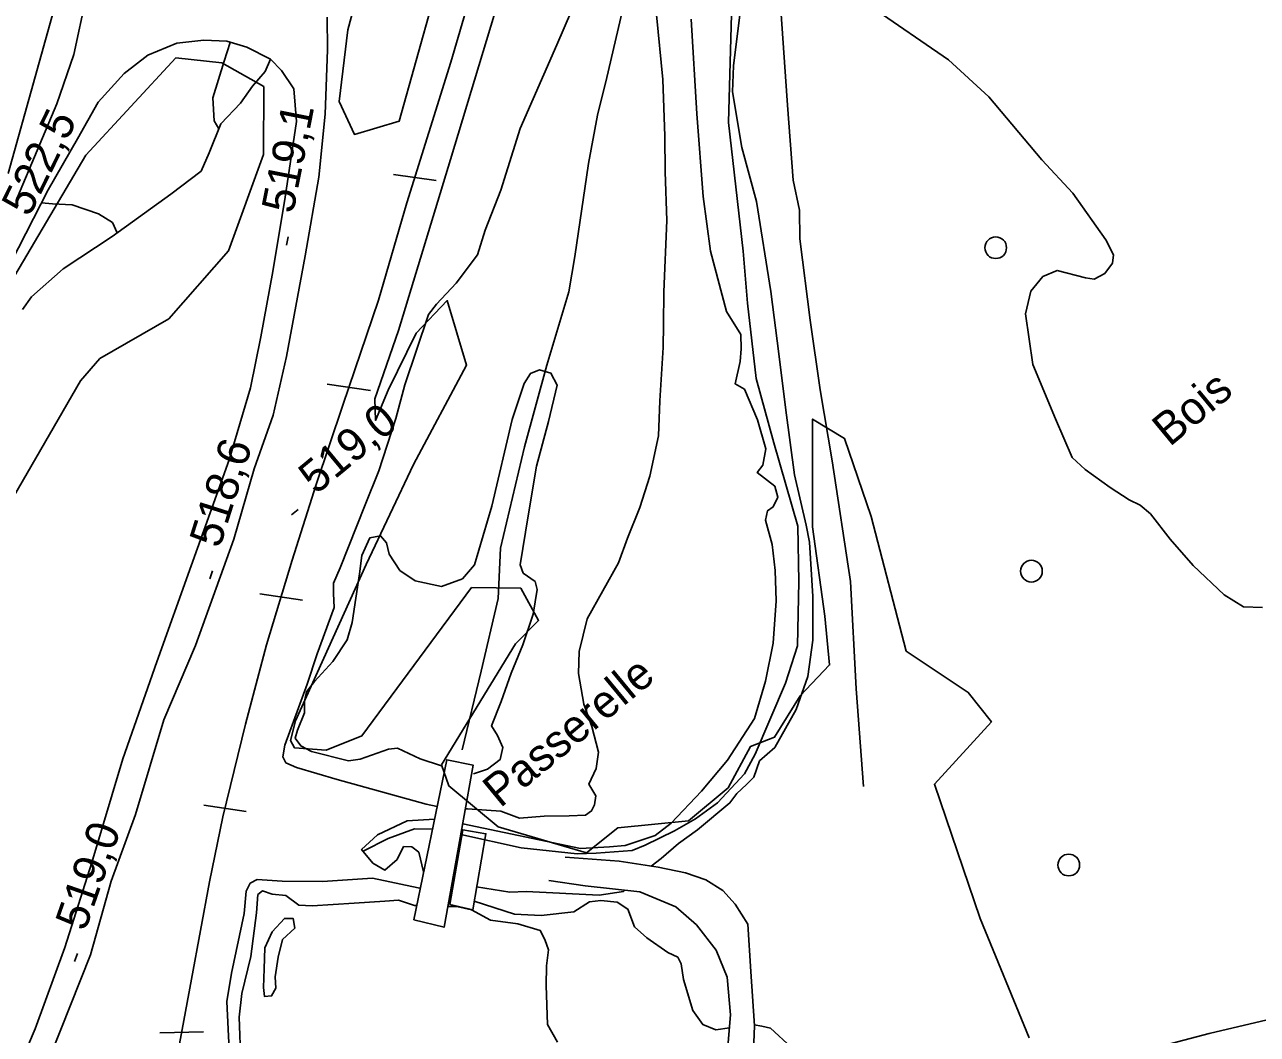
# Model space of a CAD drawing. Extents: x 347059 to 352153, y 6073752 to 6078601.
# Drawn here: x 347588.7 to 347759, y 6075388.2 to 6075527.7 of the extents above; entities that cross this region are included whole.
import ezdxf

# ---------------------------------------------------------------- set-up
doc = ezdxf.new("R2010")
doc.units = 0
for name, color, linetype in [('Level 1', 7, 'Continuous'), ('Level 19', 7, 'Continuous'), ('Level 2', 7, 'Continuous'), ('Level 22', 7, 'Continuous'), ('Level 23', 7, 'Continuous'), ('Level 26', 7, 'Continuous'), ('Level 3', 7, 'Continuous'), ('Level 31', 7, 'Continuous'), ('Level 36', 7, 'Continuous'), ('Level 4', 7, 'Continuous'), ('Level 44', 7, 'Continuous'), ('Level 54', 7, 'Continuous')]:
    doc.layers.add(name, color=color, linetype=linetype)

msp = doc.modelspace()

# ---------------------------------------------------------------- linework, layer by layer
at = {"layer": 'Level 1'}
for points in [[(347652.33, 6075499.3), (347654.48, 6075504.82), (347657.14, 6075513.31), (347662.23, 6075524.88), (347669.46, 6075541.69), (347673.43, 6075553.21), (347674.57, 6075556.8), (347676.01, 6075557.93), (347677.25, 6075556.76), (347677.37, 6075552.62), (347676.98, 6075547), (347676.29, 6075536.62), (347676, 6075529.02), (347676.85, 6075520.07), (347677.13, 6075512.28), (347677.18, 6075507.36), (347677.42, 6075500.6), (347676.99, 6075490.74), (347676.94, 6075486.27)], [(347615.52, 6075513.28), (347614.88, 6075514.4), (347614.66, 6075517.57), (347616.25, 6075522.63), (347617.08, 6075525.18), (347617.09, 6075525.23)], [(347645.68, 6075419.67), (347644.16, 6075420.01), (347638.69, 6075421.53), (347631.86, 6075423.39), (347626.26, 6075425.06), (347624.77, 6075425.71), (347624.34, 6075426.55), (347624.64, 6075428.14), (347627.73, 6075436.57), (347629.09, 6075440.77), (347631.47, 6075447.15), (347631.36, 6075449.07), (347631.35, 6075450.53), (347632.29, 6075452.65), (347635.71, 6075461.35), (347637.63, 6075466.02), (347639.95, 6075473.28), (347641.2, 6075477.93), (347644.49, 6075487.61), (347645.59, 6075489.05), (347648.3, 6075491.96), (347651.26, 6075495.87), (347652.33, 6075499.3)], [(347676.94, 6075486.27), (347676.92, 6075483.05), (347676.44, 6075475.69), (347676.28, 6075470.86), (347675.08, 6075465.32), (347673.7, 6075460.98), (347671.97, 6075456.73), (347670.75, 6075453.32), (347666.39, 6075445.58), (347665.3, 6075441.06), (347665.23, 6075438.06), (347665.93, 6075433.82), (347667.04, 6075430.71), (347667.96, 6075427.19), (347667.67, 6075424.94), (347666.65, 6075422.76), (347667.6, 6075421.14), (347667.41, 6075419.91), (347667.03, 6075419.06), (347666.2, 6075418.47), (347663.94, 6075418.39), (347660.46, 6075418.33), (347657.04, 6075418.05), (347654.47, 6075419.02), (347649.87, 6075419.36), (347649.59, 6075419.34)], [(347616.93, 6075386.06), (347616.61, 6075392.75), (347617.27, 6075396.65), (347619.02, 6075404.91), (347619.31, 6075407.96), (347619.86, 6075409.08), (347620.8, 6075409.58), (347624.24, 6075409.35), (347629.84, 6075409.29), (347636.75, 6075409.76), (347643.08, 6075408.43), (347643.34, 6075408.37)], [(347647.43, 6075407.42), (347647.64, 6075407.37)], [(347650.79, 6075406.59), (347656.36, 6075404.78), (347660.04, 6075404.6), (347664.59, 6075405.14), (347666.72, 6075406.49), (347668.29, 6075406.71), (347670.55, 6075406.44), (347672.02, 6075405.5), (347672.96, 6075403.07), (347674.66, 6075401.52), (347677.57, 6075399.5), (347678.92, 6075398.87), (347679.42, 6075397.94), (347679.73, 6075395.79), (347681.02, 6075391.5), (347682.39, 6075389.54), (347684.21, 6075388.82), (347686.08, 6075389.11)], [(347689.51, 6075389.52), (347690.57, 6075389.32), (347691.73, 6075389.07), (347694.65, 6075386.39), (347695.16, 6075384.8), (347696.77, 6075380.77), (347697.8, 6075378.41), (347700.19, 6075375.55), (347702.56, 6075374.82), (347704.49, 6075375.6), (347705.09, 6075376.5), (347705.84, 6075376.58), (347707.63, 6075373.43)]]:
    msp.add_lwpolyline(points, dxfattribs=at)
at = {"layer": 'Level 19'}
for points in [[(347587.68, 6075503.86), (347593.13, 6075516.73), (347595.49, 6075523.54), (347597.17, 6075531.51)], [(347630.5, 6075528.69), (347630.54, 6075524.17), (347630.22, 6075515.32), (347629.34, 6075506.59), (347627.42, 6075495.74), (347624.86, 6075481.84), (347623, 6075473.71), (347620.39, 6075466.29), (347617.6, 6075456.6), (347612.3, 6075441.92), (347607.89, 6075431.66), (347604, 6075418.58), (347600.64, 6075409.38), (347597.78, 6075399.16), (347589.46, 6075378.31)], [(347586.72, 6075380.96), (347590.11, 6075388.97), (347594.23, 6075400.2), (347597.98, 6075411.94), (347602.24, 6075426.25), (347606.96, 6075439.67), (347611.68, 6075452.92), (347616.94, 6075467.56), (347619.9, 6075477.49), (347621.31, 6075484.55), (347622.98, 6075493.59), (347624.67, 6075503.84), (347626.24, 6075514.31), (347625.87, 6075518.78), (347624.19, 6075521.35), (347622.63, 6075522.89), (347619.37, 6075524.56), (347616.62, 6075525.37), (347613.45, 6075525.53), (347609.72, 6075525.11), (347605.7, 6075523.46), (347602.42, 6075520.94), (347598.84, 6075516.94), (347595.99, 6075511.91), (347591.94, 6075504.86), (347586.83, 6075494.84)], [(347663.35, 6075412.65), (347670.82, 6075412.1), (347676.22, 6075411.29), (347680, 6075410.52), (347682.83, 6075409.53), (347685.16, 6075408.05), (347686.86, 6075406.17), (347688.62, 6075403.43), (347689.05, 6075396.88), (347689.52, 6075389.39), (347689.23, 6075381.39)], [(347661.12, 6075409.43), (347666.13, 6075408.73), (347673.69, 6075407.89), (347678.68, 6075405.8), (347681.51, 6075403.31), (347684.24, 6075399.81), (347685.76, 6075396.11), (347686.24, 6075390.9), (347685.56, 6075383.26), (347684.33, 6075376.97), (347683.89, 6075375.19), (347682.62, 6075370.18), (347681.29, 6075363.47), (347679.94, 6075354.9), (347679.94, 6075354.9), (347679.03, 6075348.13), (347677.75, 6075337.71), (347677.34, 6075335.16), (347674.08, 6075335.3), (347671.55, 6075336.83), (347669.29, 6075339.28), (347668.04, 6075341.6)]]:
    msp.add_lwpolyline(points, dxfattribs=at)
at = {"layer": 'Level 2'}
for points in [[(347705.63, 6075530.16), (347716.36, 6075522.8), (347721.92, 6075517.68), (347729.24, 6075508.98), (347733.54, 6075504.41), (347738.1, 6075497.93), (347739.14, 6075495.87), (347739.03, 6075494.72), (347737.95, 6075493.29), (347736.49, 6075492.49), (347735.27, 6075492.68), (347731.36, 6075493.71), (347729.39, 6075492.89), (347727.74, 6075490.86), (347727.01, 6075487.73), (347728.02, 6075480.72), (347731.15, 6075473.23), (347733.43, 6075467.9), (347735.23, 6075466.2), (347738.71, 6075463.75), (347741.32, 6075462.04)], [(347680.8, 6075528.42), (347681.56, 6075515.37), (347682.46, 6075503.91), (347683.45, 6075496.4), (347685.68, 6075488.06), (347687.67, 6075484.87), (347687.7, 6075482.88), (347687.54, 6075481.14), (347686.87, 6075478.04), (347688.14, 6075477.34), (347689.95, 6075473.07), (347691.12, 6075469.07), (347690.68, 6075466.83), (347689.92, 6075465.8), (347692.33, 6075463.9), (347692.78, 6075462.39), (347692.13, 6075461.05)], [(347696.7, 6075458.51), (347695.07, 6075465.49), (347693.85, 6075474.41), (347692.9, 6075482.2), (347691.8, 6075490.82), (347689.8, 6075503.26), (347687.78, 6075510.71), (347686.51, 6075518.38), (347686.63, 6075521.97), (347687.53, 6075529.01)], [(347601.47, 6075498.92), (347600.83, 6075500.33), (347598.88, 6075501.53), (347595.25, 6075502.8), (347592.53, 6075502.9), (347591.02, 6075503.05)], [(347646.26, 6075425.3), (347643.33, 6075426.27), (347640.22, 6075427.72), (347638.96, 6075427.61), (347635.05, 6075426.19), (347633.42, 6075425.99), (347628.31, 6075427.25), (347626.84, 6075428.04), (347626.06, 6075429.13), (347626.39, 6075430.2), (347627.35, 6075432.6), (347627.36, 6075434.21), (347627.63, 6075435.5), (347628.72, 6075436.94), (347631.27, 6075439.71), (347633.25, 6075442.68), (347633.93, 6075445.11), (347634.94, 6075451.82), (347635.25, 6075454.35), (347636.39, 6075456.8), (347637.87, 6075457.04), (347638.66, 6075456.09), (347639.03, 6075454.53), (347640.51, 6075452.27), (347642.65, 6075450.84), (347646.27, 6075450.08), (347649.17, 6075451.13), (347650.83, 6075453.03), (347653.23, 6075461.16), (347656.07, 6075473.13), (347657.72, 6075478.1), (347658.59, 6075479.49), (347659.84, 6075479.98), (347661.4, 6075479.53), (347662.27, 6075477.85), (347661.05, 6075472.83), (347659.43, 6075466.68), (347658.26, 6075459.84), (347657.17, 6075453.05), (347657.58, 6075451.92), (347659.24, 6075450.75), (347659.5, 6075449.63), (347658.95, 6075446.24), (347657.51, 6075441.98), (347655.89, 6075438.1), (347654.55, 6075434.19), (347653.2, 6075430.8), (347654.03, 6075429.48), (347654.76, 6075427.81), (347654.38, 6075426.16), (347652.63, 6075424.85), (347650.7, 6075424.18)], [(347692.13, 6075461.05), (347691.34, 6075460.53), (347691.07, 6075459.23), (347692, 6075455.85), (347692.4, 6075452.29), (347692.52, 6075448.09), (347692.11, 6075442.25), (347691.08, 6075436.99), (347689.56, 6075431.84), (347685.82, 6075426.08), (347682.23, 6075421.77), (347678.03, 6075417.38), (347675.79, 6075415.67), (347671.67, 6075414.28), (347669.5, 6075414.1), (347665.49, 6075413.88), (347649.22, 6075417.3)], [(347741.32, 6075462.04), (347742.85, 6075461.31), (347744.27, 6075460.08), (347747, 6075456.61), (347750.15, 6075452.96), (347754.43, 6075448.9), (347757.12, 6075447.26), (347759.73, 6075447.15)], [(347675.28, 6075411.43), (347676.63, 6075412.49), (347679.02, 6075414.57), (347681.64, 6075416.47), (347686.14, 6075420.17), (347687.08, 6075421.48), (347688.41, 6075422.7), (347689.46, 6075423.72), (347690.25, 6075425.97), (347692.36, 6075427.84), (347695.3, 6075433.08), (347696.92, 6075437.64), (347697.62, 6075442.64), (347697.61, 6075448.67), (347697.14, 6075456.2), (347696.7, 6075458.51)], [(347645.31, 6075417.9), (347641.56, 6075417.68), (347637.42, 6075415.78), (347635.24, 6075413.75), (347636.81, 6075411.83), (347638.45, 6075410.9), (347640.15, 6075412.36), (347641.05, 6075414.13), (347642.2, 6075414.12), (347643.16, 6075413.36), (347643.81, 6075410.63)], [(347647.74, 6075409.09), (347647.94, 6075409.06)], [(347651.14, 6075408.56), (347655.74, 6075407.85), (347657.96, 6075407.95), (347668.05, 6075407.41), (347671.43, 6075407.91), (347671.64, 6075408.12)], [(347642.85, 6075405.99), (347642.55, 6075406.01), (347640.35, 6075406.72), (347638.43, 6075406.6), (347634.2, 6075406.32), (347628.42, 6075405.96), (347626.58, 6075406.05), (347624.79, 6075407.38), (347622.9, 6075407.55), (347621.54, 6075408.04), (347620.9, 6075407.51), (347620.73, 6075404.97), (347619.94, 6075398.97), (347618.71, 6075393.82), (347618.32, 6075390.56), (347618.54, 6075384.33)], [(347662.29, 6075387.12), (347660.91, 6075389.58), (347660.75, 6075394.94), (347660.79, 6075397.64), (347661.08, 6075399.88), (347660.55, 6075401.32), (347659.93, 6075402.56), (347656.85, 6075403.48), (347653.06, 6075403.97), (347650.42, 6075405.38), (347648.38, 6075405.85), (347647.15, 6075405.84)], [(347621.69, 6075394.66), (347621.76, 6075397.25), (347621.86, 6075400.16), (347622.87, 6075402.34), (347624.58, 6075404.22), (347625.79, 6075404.19), (347626, 6075402.87), (347624.32, 6075401.32), (347623.69, 6075398.86), (347623.28, 6075396.14), (347623.38, 6075394.59), (347622.8, 6075393.51), (347621.82, 6075393.43), (347621.69, 6075394.66)]]:
    msp.add_lwpolyline(points, dxfattribs=at)
at = {"layer": 'Level 22'}
for points in [[(347704.6, 6075422.45), (347703.58, 6075435.93), (347702.82, 6075450.77), (347700.28, 6075467.42), (347698.63, 6075477.24), (347697.24, 6075486.83), (347695.82, 6075498.06), (347695.74, 6075502.02), (347694.86, 6075506.19), (347694.1, 6075516.55), (347692.97, 6075532.44), (347692.17, 6075545.42), (347691.99, 6075558.55), (347692.74, 6075566.82), (347693.27, 6075572.27), (347694.1, 6075584.23), (347694.82, 6075596.85), (347695.19, 6075610.31), (347695.4, 6075619.03), (347696.28, 6075626.27), (347697.12, 6075631.98)], [(347649.12, 6075427.51), (347651.78, 6075438.36), (347654.13, 6075448.42), (347654.43, 6075455.34), (347657.77, 6075469.35), (347660.82, 6075480.62), (347663.87, 6075490.75), (347664.71, 6075495.65), (347666.62, 6075508.51), (347667.84, 6075515.17), (347669.11, 6075520.36), (347671.58, 6075530.83)]]:
    msp.add_lwpolyline(points, dxfattribs=at)
at = {"layer": 'Level 23'}
for p, q in [((347639.63, 6075506.99), (347645.56, 6075506.12)), ((347630.49, 6075478.01), (347636.45, 6075477.14)), ((347621.16, 6075449.05), (347627.08, 6075448.18)), ((347613.42, 6075419.86), (347619.31, 6075419)), ((347607.35, 6075388.43), (347613.4, 6075388.56))]:
    msp.add_line(p, q, dxfattribs=at)
msp.add_lwpolyline([(347609.23, 6075382.41), (347611.75, 6075395.83), (347614.2, 6075409.25), (347616.07, 6075418.24), (347619.2, 6075431.04), (347622.12, 6075441.98), (347625.66, 6075453.7), (347628.94, 6075464.13), (347632.63, 6075475.13), (347637.59, 6075489.59), (347641.51, 6075503.06), (347647.56, 6075522.49), (347652.71, 6075540.14), (347658.57, 6075559.61), (347664.03, 6075579.1), (347668.39, 6075594.32), (347673.93, 6075613.79), (347677.32, 6075624.7), (347681.41, 6075639.01), (347686.09, 6075655.26), (347691.07, 6075673.19)], dxfattribs=at)
at = {"layer": 'Level 26'}
msp.add_lwpolyline([(347642.44, 6075404.01), (347647.01, 6075426.12), (347650.68, 6075425.36), (347646.63, 6075403), (347642.44, 6075404.01)], dxfattribs=at)
at = {"layer": 'Level 3'}
for p, q in [((347624.87, 6075497.21), (347625.11, 6075498.38)), ((347625.57, 6075459.94), (347626.49, 6075460.71)), ((347614.28, 6075451.1), (347614.64, 6075452.24)), ((347595.56, 6075398.24), (347595.96, 6075399.38))]:
    msp.add_line(p, q, dxfattribs=at)
at = {"layer": 'Level 31'}
msp.add_lwpolyline([(347647.42, 6075406.13), (347649.23, 6075416.46), (347652.42, 6075415.9), (347650.59, 6075405.42), (347647.42, 6075406.13)], dxfattribs=at)
at = {"layer": 'Level 36'}
for centre in [(347722.87, 6075496.86), (347727.81, 6075452.18), (347732.96, 6075411.59)]:
    msp.add_circle(centre, 1.5, dxfattribs=at)
at = {"layer": 'Level 4'}
for points in [[(347648.95, 6075415.81), (347657.27, 6075413.98), (347665.04, 6075413.15), (347667.66, 6075413.21), (347672.63, 6075413.61), (347674.44, 6075414.34), (347678.5, 6075416.32), (347681.39, 6075417.98), (347684.44, 6075420.16), (347688.16, 6075424.2), (347689.63, 6075426.91), (347693.84, 6075436.71), (347695.48, 6075441.85), (347695.68, 6075450.77), (347695.54, 6075458.4), (347692.21, 6075469.91), (347689.79, 6075478.77), (347688.55, 6075489.18), (347687.97, 6075496.36), (347685.95, 6075514.17), (347686.36, 6075529.1)], [(347635.45, 6075413.48), (347638.93, 6075415.26), (347642.57, 6075416.58), (347645.03, 6075416.56)]]:
    msp.add_lwpolyline(points, dxfattribs=at)
at = {"layer": 'Level 44'}
for points in [[(347659.83, 6075580.65), (347655.4, 6075562.61), (347645.14, 6075531.14), (347640.41, 6075514.32), (347634.25, 6075512.5), (347632.16, 6075517.04), (347633.33, 6075526.97), (347640.17, 6075552.26), (347643.3, 6075564.51), (347644.52, 6075572.84), (347650.63, 6075594.11), (347654.11, 6075610.07), (347657.18, 6075616.16), (347660.04, 6075616.51), (347665.11, 6075606.38), (347661.76, 6075594.3), (347660.7, 6075587.81), (347659.83, 6075580.65)], [(347582.93, 6075565.96), (347589.99, 6075554.63), (347595.87, 6075543.79), (347593.87, 6075533.84), (347586.4, 6075507.09)], [(347650.41, 6075449.91), (347635.28, 6075429.44), (347630.35, 6075427.45), (347625.98, 6075427.77), (347625.41, 6075428.79), (347626.12, 6075431.49), (347635.89, 6075453.08), (347642.42, 6075466.89), (347649.76, 6075480.65), (347647.07, 6075489.55), (347642.76, 6075485.05), (347638.93, 6075477.2), (347637.18, 6075472.99), (347637.08, 6075475.99), (347640.34, 6075485.4), (347647.52, 6075509.06), (347655.34, 6075534.94)], [(347587.33, 6075493.01), (347597.14, 6075509.64), (347609.58, 6075523.09), (347615.91, 6075522.4), (347621.74, 6075519.11), (347621.7, 6075509.73), (347616.83, 6075496.42), (347608.58, 6075487.02), (347599.05, 6075481.54), (347596.39, 6075478.48), (347585.95, 6075460.37)], [(347727.51, 6075387.72), (347720.72, 6075404.19), (347714.4, 6075422.75), (347722.28, 6075431.37), (347719.07, 6075435.44), (347710.51, 6075441.13), (347705.67, 6075459.74), (347701.97, 6075470.52), (347697.56, 6075473.19), (347697.54, 6075458.29), (347699.26, 6075445.95), (347699.91, 6075439.22), (347695.85, 6075434.96), (347692.32, 6075429.27), (347688.99, 6075427.97), (347685.88, 6075422.26), (347680.42, 6075417.69), (347670.65, 6075416.71), (347666.32, 6075413.28), (347654.11, 6075416.88), (347647.29, 6075422.51), (347646.28, 6075425.43), (347656.51, 6075442.12), (347659.71, 6075445.38), (347657.24, 6075449.84), (347650.41, 6075449.91)], [(347774.5, 6075393.5), (347752.38, 6075388.3), (347734.35, 6075383.56)]]:
    msp.add_lwpolyline(points, dxfattribs=at)
at = {"layer": 'Level 54'}
msp.add_lwpolyline([(347588.38, 6075488.34), (347589.6, 6075490.07), (347593.99, 6075493.93), (347600.77, 6075498.41), (347608.88, 6075504.27), (347613.05, 6075507.41), (347614.17, 6075509.97), (347615.8, 6075513.95), (347618.49, 6075516.8), (347620.17, 6075519.16), (347621.9, 6075521.18), (347622.63, 6075522.89)], dxfattribs=at)

# ---------------------------------------------------------------- texts
at = {"layer": 'Level 26'}
msp.add_text('Passerelle', height=4.5, rotation=39.568, dxfattribs=at).set_placement((347654.39, 6075419.38))
at = {"layer": 'Level 3'}
for s, rotation, p in [('522,5', 63.7428, (347589.32, 6075500.97)), ('519,1', 78.7871, (347625.77, 6075501.44)), ('519,0', 39.62, (347628.93, 6075462.66)), ('518,6', 72.4382, (347615.63, 6075455.2)), ('519,0', 70.6795, (347597.04, 6075402.31))]:
    msp.add_text(s, height=4.5, rotation=rotation, dxfattribs=at).set_placement(p)
at = {"layer": 'Level 44'}
msp.add_text('Bois', height=4.5, rotation=39.568, dxfattribs=at).set_placement((347746.9, 6075469.27))

doc.saveas('drawing.dxf')
